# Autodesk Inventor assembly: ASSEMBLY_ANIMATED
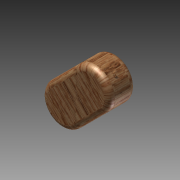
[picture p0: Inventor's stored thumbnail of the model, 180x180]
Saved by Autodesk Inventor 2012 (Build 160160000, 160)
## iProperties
Created: 2011-01
Part Number: ASSEMBLY_ANIMATED
Document SubType Name: Assembly
Designer: Microsoft
Author: Microsoft
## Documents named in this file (6)
- C:\Users\David\Desktop\Playground\3D work\Locket\ASSEMBLY_ANIMATED.iam
- C:\Users\David\Desktop\Playground\3D work\Locket\BASE2-TOP.ipt
- C:\Users\David\Desktop\Playground\3D work\Locket\BASE2.ipt
- C:\Users\David\Desktop\Playground\3D work\Locket\TOP2.ipt
- C:\Users\David\Desktop\Playground\3D work\Locket\BASE1.ipt
- C:\Users\David\Desktop\Playground\3D work\Locket\TOP1.ipt
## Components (5 placed, 5 different names)
1. BASE2-TOP:1 — Mate:3, Flush:2, Mate:4, Mate:5, Mate:7
2. BASE2:1 — Mate:3, Flush:2, Mate:4, Mate:6, Mate:8, Angle:1
3. TOP2:1 — Mate:3, Mate:5, Mate:6, Flush:4, Flush:5
4. BASE1:1 — Mate:1, Mate:2, Mate:7, Flush:4, Mate:8, Flush:6, Flush:7
5. TOP1:1 — Mate:1, Mate:2, Flush:5, Angle:2, Mate:3
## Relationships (16: Mate 9, Flush 5, Angle 2)
- Mate:1: BASE1:1 ↔ TOP1:1
- Mate:2: BASE1:1 ↔ TOP1:1
- Mate:3: BASE2-TOP:1 ↔ BASE2:1
- Flush:2: BASE2-TOP:1 ↔ BASE2:1
- Mate:4: BASE2-TOP:1 ↔ BASE2:1
- Mate:3: TOP2:1 ↔ TOP1:1
- Mate:5: BASE2-TOP:1 ↔ TOP2:1
- Mate:6: BASE2:1 ↔ TOP2:1
- Mate:7: BASE2-TOP:1 ↔ BASE1:1
- Flush:4: TOP2:1 ↔ BASE1:1
- Mate:8: BASE2:1 ↔ BASE1:1
- Flush:5: TOP2:1 ↔ TOP1:1
- Flush:6: BASE1:1
- Angle:1: BASE2:1
- Flush:7: BASE1:1
- Angle:2: TOP1:1
